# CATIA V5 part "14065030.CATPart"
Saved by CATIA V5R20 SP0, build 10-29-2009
Part number: 14065030
Definition: NONE
Nomenclature: 14065030
Source: Unknown
Description: 14065030
Bounding box of the stored display mesh (mm): x -15 to 60, y -46.5 to 36.6, z -36.6 to 36.6
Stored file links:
  C:\Users\Utente\Desktop\IO LAVORO\3D X SITO CF\X SITO\PLASTICA\RF2\14065030.CATPart
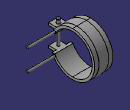
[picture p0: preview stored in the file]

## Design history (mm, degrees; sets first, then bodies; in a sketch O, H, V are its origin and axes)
Body1 "14065030" (main body)
  Solid1: solid without history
